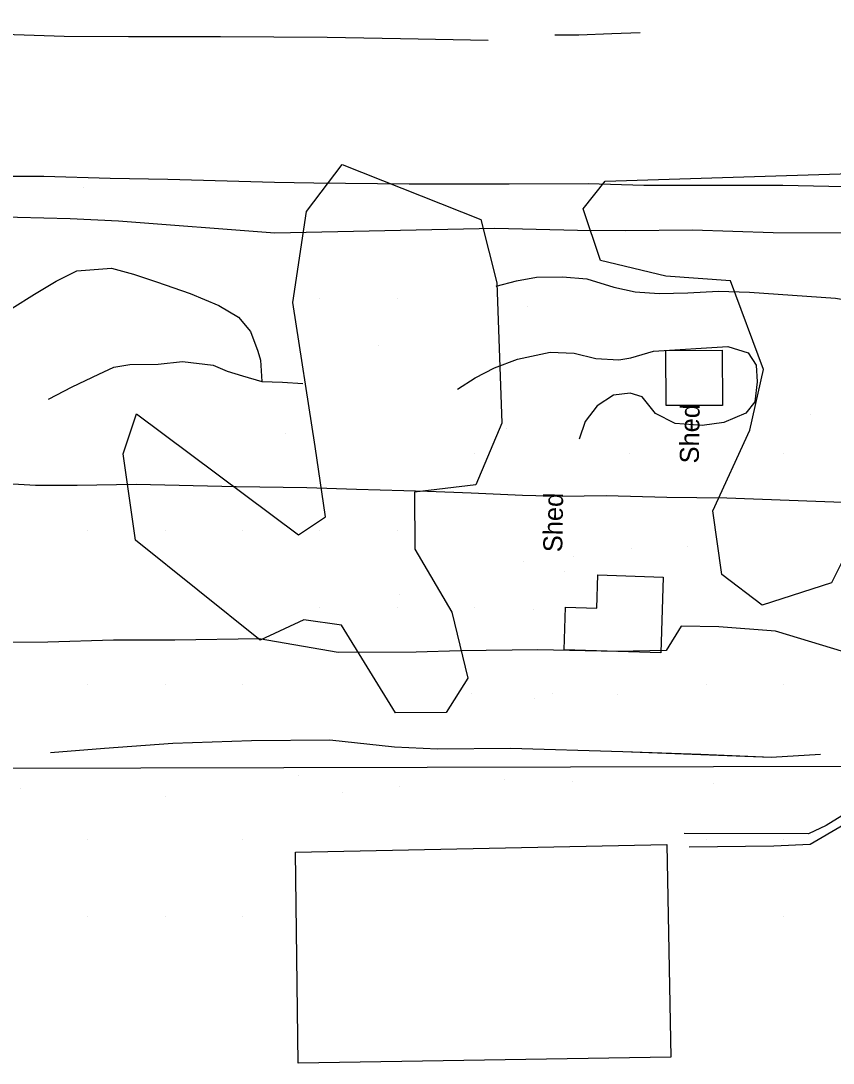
# Model space of a CAD drawing. Extents: x 19528164 to 19545171, y 7585743 to 7602745.
# Drawn here: x 19529427.7 to 19529637.7, y 7587517.2 to 7587786.8 of the extents above; entities that cross this region are included whole.
import ezdxf

# ---------------------------------------------------------------- set-up
doc = ezdxf.new("R2010")
doc.units = 0
for name, color, linetype in [('PhoBreakLine', 7, 'Continuous'), ('PhoBuilding', 7, 'Continuous'), ('PhoEdgeSidewalk', 7, 'Continuous'), ('PhoISAEPoints', 7, 'Continuous'), ('PhoNotesDesign', 7, 'Continuous'), ('PhoSurveyLimits', 7, 'Continuous'), ('PhoVegetation', 7, 'Continuous'), ('SurBreakLine', 7, 'Continuous'), ('SurEdgeEntranceUnpaved', 7, 'Continuous')]:
    doc.layers.add(name, color=color, linetype=linetype)

msp = doc.modelspace()

# ---------------------------------------------------------------- linework, layer by layer
at = {"layer": 'PhoBreakLine'}
for points in [[(19529412.92, 7587783.71), (19529438.91, 7587782.8), (19529455.47, 7587782.76), (19529479.29, 7587782.72), (19529506.87, 7587782.53), (19529525.84, 7587782.24), (19529548.54, 7587781.81)], [(19529565.74, 7587783.2), (19529571.95, 7587783.16), (19529580.53, 7587783.51), (19529587.81, 7587783.73)], [(19529420.19, 7587746.61), (19529433.66, 7587746.58), (19529450.79, 7587746.1), (19529465.72, 7587745.84), (19529493.29, 7587745.02), (19529503.44, 7587744.9), (19529528.05, 7587744.66), (19529553.91, 7587744.62), (19529574.34, 7587744.69), (19529588.8, 7587744.24), (19529624.68, 7587744.31), (19529640.57, 7587743.93), (19529668.81, 7587743.19), (19529693.9, 7587741.96), (19529711.72, 7587741.66)], [(19529156.27, 7587739.82), (19529168.3, 7587739.53), (19529192.58, 7587740.59), (19529208.56, 7587740.78), (19529236.73, 7587740.12), (19529269.19, 7587739.6), (19529293.66, 7587738.67), (19529340.18, 7587738.62), (19529352.73, 7587738.2), (19529419.89, 7587736.21), (19529440.4, 7587735.64), (19529452.89, 7587735.05), (19529493.33, 7587731.91), (19529550.24, 7587733.18), (19529571.65, 7587732.68), (19529583.99, 7587732.56), (19529601.39, 7587732.73), (19529622.17, 7587732.03), (19529688.78, 7587731.89)], [(19529420.84, 7587709.31), (19529425.4, 7587712.45), (19529431.19, 7587716.07), (19529436.83, 7587719.43), (19529442.18, 7587722.14), (19529451.15, 7587722.85), (19529456.8, 7587721.29), (19529462.75, 7587719.24), (19529471.46, 7587716.28), (19529478.91, 7587713.15), (19529483.95, 7587710.15), (19529487.09, 7587706.46), (19529488.97, 7587701.33), (19529489.66, 7587699), (19529489.97, 7587693.5)], [(19529550.6, 7587718.15), (19529555.84, 7587719.55), (19529561.02, 7587720.51), (19529567.7, 7587720.6), (19529573.99, 7587720.03), (19529581.01, 7587717.92), (19529586.52, 7587716.65), (19529592.7, 7587716.29), (19529600.13, 7587716.46), (19529608.05, 7587716.82), (19529616.13, 7587716.64)], [(19529616.13, 7587716.64), (19529638.34, 7587715.08), (19529653.91, 7587712.56), (19529689.77, 7587709.6), (19529704.19, 7587707.22), (19529715.24, 7587702.13), (19529721.86, 7587694.89), (19529726.26, 7587688.26)], [(19529540.6, 7587691.48), (19529545.12, 7587694.42), (19529550.15, 7587697.06), (19529556.13, 7587699.24), (19529564.54, 7587701.07), (19529570.75, 7587700.82), (19529576.39, 7587699.48), (19529582.28, 7587699.14), (19529585.44, 7587699.63), (19529591.23, 7587701.34), (19529610.53, 7587702.51), (19529615.74, 7587700.9), (19529617.78, 7587697.74), (19529618.1, 7587693.4), (19529617.46, 7587688.23), (19529615.17, 7587685.31), (19529609.49, 7587682.91), (19529603.87, 7587682.15), (19529596.83, 7587682.62), (19529591.8, 7587685.26), (19529588.33, 7587689.5), (19529585.2, 7587690.48), (19529580.93, 7587689.94), (19529576.68, 7587687.16), (19529573.61, 7587683.19), (19529572.06, 7587678.59)], [(19529434.85, 7587688.96), (19529440.94, 7587692.11), (19529447.84, 7587695.39), (19529451.73, 7587697.24), (19529455.85, 7587697.89), (19529463.16, 7587697.94), (19529469.48, 7587698.65), (19529477.41, 7587697.68), (19529481.06, 7587696.17), (19529484.97, 7587694.92), (19529489.97, 7587693.5), (19529495.32, 7587693.31), (19529500.6, 7587693.02)], [(19529661.43, 7587662.5), (19529651.64, 7587662.52), (19529642.47, 7587662.11), (19529610.25, 7587663.29), (19529594.75, 7587663.47), (19529579.01, 7587663.89), (19529567.69, 7587663.74), (19529557.42, 7587664.03), (19529544.08, 7587664.65), (19529532.79, 7587665.08), (19529514.51, 7587665.52), (19529501.64, 7587666.02), (19529483.38, 7587666.28), (19529457.48, 7587666.84), (19529442.28, 7587666.62), (19529431.44, 7587666.63), (19529419.74, 7587667.28)], [(19529657.07, 7587622.63), (19529640.76, 7587623.46), (19529622.79, 7587628.88), (19529608.14, 7587630), (19529598.42, 7587630.22), (19529594.53, 7587623.93), (19529581.77, 7587623.64), (19529561.39, 7587624.06), (19529541.38, 7587623.79), (19529529.93, 7587623.48), (19529509.74, 7587623.42), (19529489.3, 7587626.92), (19529467.48, 7587626.59), (19529451.67, 7587626.55), (19529434.68, 7587626.08), (19529420.65, 7587625.99), (19529408.42, 7587625.79)]]:
    msp.add_lwpolyline(points, dxfattribs=at)
at = {"layer": 'PhoBuilding'}
for points in [[(19529594.53, 7587687.27), (19529594.47, 7587701.54), (19529609.05, 7587701.6), (19529609.11, 7587687.33)], [(19529593.16, 7587623.29), (19529568.14, 7587624.1), (19529568.5, 7587635.09), (19529576.62, 7587634.83), (19529576.9, 7587643.45), (19529593.8, 7587642.9)], [(19529595.79, 7587518.74), (19529499.41, 7587517.18), (19529498.7, 7587571.74), (19529594.71, 7587573.72)]]:
    msp.add_lwpolyline(points, close=True, dxfattribs=at)
at = {"layer": 'PhoEdgeSidewalk'}
for points in [[(19529671, 7587600.46), (19529653.97, 7587589.79), (19529635.89, 7587578.66), (19529631.36, 7587576.54), (19529599.21, 7587576.57)], [(19529600.5, 7587573.15), (19529622.4, 7587573.43), (19529631.81, 7587573.83), (19529655.83, 7587587.91), (19529673.53, 7587598.74)]]:
    msp.add_lwpolyline(points, dxfattribs=at)
at = {"layer": 'PhoISAEPoints'}
for p, q in [((19529443.76, 7587743.7), (19529443.76, 7587743.7)), ((19529505, 7587715), (19529505, 7587715)), ((19529505, 7587715), (19529505, 7587715)), ((19529525, 7587715), (19529525, 7587715)), ((19529525, 7587715), (19529525, 7587715)), ((19529558.66, 7587712.99), (19529558.66, 7587712.99)), ((19529520.26, 7587702.8), (19529520.26, 7587702.8)), ((19529631.89, 7587684.87), (19529631.89, 7587684.87)), ((19529496.09, 7587679.99), (19529496.09, 7587679.99)), ((19529553.36, 7587681.34), (19529553.36, 7587681.34)), ((19529545, 7587675), (19529545, 7587675)), ((19529585, 7587675), (19529585, 7587675)), ((19529585, 7587675), (19529585, 7587675)), ((19529625, 7587675), (19529625, 7587675)), ((19529445, 7587655), (19529445, 7587655)), ((19529445, 7587655), (19529445, 7587655)), ((19529445, 7587655), (19529445, 7587655)), ((19529465, 7587655), (19529465, 7587655)), ((19529465, 7587655), (19529465, 7587655)), ((19529465, 7587655), (19529465, 7587655)), ((19529485, 7587655), (19529485, 7587655)), ((19529485, 7587655), (19529485, 7587655)), ((19529485, 7587655), (19529485, 7587655)), ((19529505, 7587655), (19529505, 7587655)), ((19529505, 7587655), (19529505, 7587655)), ((19529505, 7587655), (19529505, 7587655)), ((19529525, 7587655), (19529525, 7587655)), ((19529525, 7587655), (19529525, 7587655)), ((19529525, 7587655), (19529525, 7587655)), ((19529585.62, 7587650.29), (19529585.62, 7587650.29)), ((19529599.98, 7587650.86), (19529599.98, 7587650.86)), ((19529570.58, 7587648.36), (19529570.58, 7587648.36)), ((19529557.74, 7587647.02), (19529557.74, 7587647.02)), ((19529568.16, 7587644.29), (19529568.16, 7587644.29)), ((19529525.65, 7587638.28), (19529525.65, 7587638.28)), ((19529505, 7587635), (19529505, 7587635)), ((19529505, 7587635), (19529505, 7587635)), ((19529525, 7587635), (19529525, 7587635)), ((19529545, 7587635), (19529545, 7587635)), ((19529545, 7587635), (19529545, 7587635)), ((19529545, 7587635), (19529545, 7587635)), ((19529560.35, 7587634.4), (19529560.35, 7587634.4))]:
    msp.add_line(p, q, dxfattribs=at)
at = {"layer": 'PhoSurveyLimits'}
msp.add_lwpolyline([(19532927.8, 7588415.02), (19531060.74, 7587591.82), (19530315.47, 7587591.82), (19529733.27, 7587594.16), (19528768.59, 7587591.82), (19528359.06, 7587591.82), (19528383.91, 7589187.36), (19529003.19, 7589193.14), (19529457, 7588986.74), (19529383.8, 7588810.24), (19529181.3, 7588824.95), (19528822.49, 7588987.64), (19528768.59, 7587951.55), (19530119.99, 7587951.55), (19530497.83, 7588049.69), (19530813.08, 7588141.83), (19530826.36, 7590306.58)], dxfattribs=at)
at = {"layer": 'PhoVegetation'}
for points in [[(19529489.57, 7587626.56), (19529457.29, 7587652.45), (19529454.09, 7587674.77), (19529457.6, 7587685.17), (19529499.49, 7587653.87), (19529506.49, 7587658.45), (19529503.76, 7587676.69), (19529497.97, 7587713.96), (19529501.57, 7587737.45), (19529510.78, 7587749.6), (19529546.59, 7587735.39), (19529550.72, 7587718.98), (19529552.06, 7587682.75), (19529545.33, 7587666.74), (19529529.49, 7587664.88), (19529529.51, 7587650.17), (19529539.11, 7587633.84), (19529543.24, 7587616.76), (19529537.66, 7587607.87), (19529524.51, 7587607.79), (19529510.55, 7587630.5), (19529500.86, 7587631.84)], [(19529489.57, 7587626.56), (19529457.29, 7587652.45), (19529454.09, 7587674.77), (19529457.6, 7587685.17), (19529499.49, 7587653.87), (19529506.49, 7587658.45), (19529503.76, 7587676.69), (19529497.97, 7587713.96), (19529501.57, 7587737.45), (19529510.78, 7587749.6), (19529546.59, 7587735.39), (19529550.72, 7587718.98), (19529552.06, 7587682.75), (19529545.33, 7587666.74), (19529529.49, 7587664.88), (19529529.51, 7587650.17), (19529539.11, 7587633.84), (19529543.24, 7587616.76), (19529537.66, 7587607.87), (19529524.51, 7587607.79), (19529510.55, 7587630.5), (19529500.86, 7587631.84)], [(19529489.57, 7587626.56), (19529457.29, 7587652.45), (19529454.09, 7587674.77), (19529457.6, 7587685.17), (19529499.49, 7587653.87), (19529506.49, 7587658.45), (19529503.76, 7587676.69), (19529497.97, 7587713.96), (19529501.57, 7587737.45), (19529510.78, 7587749.6), (19529546.59, 7587735.39), (19529550.72, 7587718.98), (19529552.06, 7587682.75), (19529545.33, 7587666.74), (19529529.49, 7587664.88), (19529529.51, 7587650.17), (19529539.11, 7587633.84), (19529543.24, 7587616.76), (19529537.66, 7587607.87), (19529524.51, 7587607.79), (19529510.55, 7587630.5), (19529500.86, 7587631.84)], [(19529608.94, 7587643.61), (19529606.59, 7587660.06), (19529616.14, 7587680.9), (19529619.69, 7587696.6), (19529611.14, 7587719.56), (19529594.43, 7587720.78), (19529577.56, 7587724.78), (19529573.08, 7587738.13), (19529578.8, 7587745.28), (19529675.41, 7587748.37), (19529682.64, 7587737.51), (19529688.21, 7587718.53), (19529680.27, 7587705.53), (19529661.58, 7587710.83), (19529643.02, 7587710.83), (19529641.23, 7587691.45), (19529642.48, 7587668.7), (19529642.55, 7587651.93), (19529637.3, 7587641.43), (19529619.37, 7587635.68)]]:
    msp.add_lwpolyline(points, close=True, dxfattribs=at)
at = {"layer": 'SurBreakLine'}
for points in [[(19529435.34, 7587597.52), (19529449.32, 7587598.62), (19529466.98, 7587599.91), (19529487.28, 7587600.65), (19529507.53, 7587600.82), (19529524.26, 7587599.02), (19529535.42, 7587598.5), (19529554.26, 7587598.65), (19529583.36, 7587597.76), (19529603.49, 7587597.06), (19529621.68, 7587596.32), (19529634.48, 7587597.11)], [(19529435.34, 7587597.52), (19529449.32, 7587598.62), (19529466.98, 7587599.91), (19529487.28, 7587600.65), (19529507.53, 7587600.82), (19529524.26, 7587599.02), (19529535.42, 7587598.5), (19529554.26, 7587598.65), (19529583.36, 7587597.76), (19529603.49, 7587597.07), (19529621.68, 7587596.32), (19529634.48, 7587597.11)]]:
    msp.add_lwpolyline(points, dxfattribs=at)
at = {"layer": 'SurEdgeEntranceUnpaved'}
for p, q in [((19529445, 7587615), (19529445, 7587615)), ((19529445, 7587615), (19529445, 7587615)), ((19529445, 7587615), (19529445, 7587615)), ((19529465, 7587615), (19529465, 7587615)), ((19529465, 7587615), (19529465, 7587615)), ((19529465, 7587615), (19529465, 7587615)), ((19529485, 7587615), (19529485, 7587615)), ((19529485, 7587615), (19529485, 7587615)), ((19529485, 7587615), (19529485, 7587615)), ((19529605, 7587615), (19529605, 7587615)), ((19529605, 7587615), (19529605, 7587615)), ((19529605, 7587615), (19529605, 7587615)), ((19529625, 7587615), (19529625, 7587615)), ((19529625, 7587615), (19529625, 7587615)), ((19529625, 7587615), (19529625, 7587615)), ((19529544.19, 7587612.76), (19529544.19, 7587612.76)), ((19529565.27, 7587612.69), (19529565.27, 7587612.69)), ((19529581.88, 7587612.42), (19529581.88, 7587612.42)), ((19529560.52, 7587611.45), (19529560.52, 7587611.45)), ((19529499.42, 7587591.61), (19529499.42, 7587591.61)), ((19529427.71, 7587588.14), (19529427.71, 7587588.14)), ((19529525.55, 7587588.84), (19529525.55, 7587588.84)), ((19529552.71, 7587590.44), (19529552.71, 7587590.44)), ((19529570.45, 7587590.03), (19529570.45, 7587590.03)), ((19529606.72, 7587589.57), (19529606.72, 7587589.57)), ((19529464.96, 7587586.08), (19529464.96, 7587586.08)), ((19529510.96, 7587587.07), (19529510.96, 7587587.07)), ((19529445, 7587575), (19529445, 7587575)), ((19529485, 7587575), (19529485, 7587575)), ((19529605, 7587575), (19529605, 7587575)), ((19529625, 7587575), (19529625, 7587575)), ((19529445, 7587555), (19529445, 7587555)), ((19529465, 7587555), (19529465, 7587555)), ((19529485, 7587555), (19529485, 7587555)), ((19529625, 7587555), (19529625, 7587555))]:
    msp.add_line(p, q, dxfattribs=at)

# ---------------------------------------------------------------- texts
at = {"layer": 'PhoNotesDesign'}
for p in [(19529602.97, 7587672.27), (19529567.66, 7587649.31)]:
    msp.add_text('Shed', height=4.92, rotation=89.0465, dxfattribs=at).set_placement(p)

doc.saveas('drawing.dxf')
